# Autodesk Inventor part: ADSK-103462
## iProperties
Shininess: 0.0
Created: 2000-11
Part Number: ADSK-103462
Document SubType Name: Modeling
Designer: gao
Stock Number: ADSK-103462
Density: 1 g/cm^3
Density: 0.0
Volumn: 0.0
Area: 0.0
PropertySet Name: Model Information
Control State: 0
Master: False
Checked Out: False
Author: gao
